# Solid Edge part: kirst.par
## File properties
Username: Kasutaja
Author: Kasutaja
Template: Iso Metric Part.par
Last saved by: Kasutaja
Revision: 8
Application: Solid Edge
Accuracy: 0,990
Face Style: Model Default
Fill Style: Normal
Coef. of Thermal Exp: 0.0
Thermal Conductivity: 0.0
Specific Heat: 0.0
Modulus of Elasticity: 0.0
Poisson's Ratio: 0.0
Yield Stress: 0.0
Ultimate Stress: 0.0
Elongation: 0.0
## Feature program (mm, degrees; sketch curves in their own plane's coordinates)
sketch used by "unnamed Protrusion 1" plane through (0, 0, 0) normal (0, 0, 1) x-axis (1, 0, 0)
  line (-7.5, 10) -> (7.5, 10)
  line (7.5, 10) -> (7.5, -10)
  line (7.5, -10) -> (-7.5, -10)
  line (-7.5, -10) -> (-7.5, 10)
  dimension (linear) = 7.5
  dimension (linear) = 7.5
extrude "unnamed Protrusion 1" add finite 20 along +normal
thinwall "Thinwall_2"  Thickness = 1 mm
draft "Draft_9"  Angles1 = 8 deg
fillet "Round_2" radius 3
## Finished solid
Body 1: solid body, 23 faces, 48 edges, 28 vertices.
  Faces by surface: plane 11, cylinder 8, sphere 4
  Edges by curve: line 32, circle 12, ellipse 4
Bounding box of the edges (mm; curved faces can reach further): 20.622 x 25.622 x 20.000, from (-10.3108, -12.8108, 0) to (10.3108, 12.8108, 20).
Cylindrical faces by radius (mm): R3 x8
Spherical faces by radius (mm): R3 x4
Planar faces by outward normal: +x 1, +y 1, +z 1, -x 1, -y 1, -z 2, oblique 4
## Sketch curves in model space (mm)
line (7.5, 10, 0) -> (7.5, -10, 0)
line (7.5, -10, 0) -> (-7.5, -10, 0)
line (-7.5, -10, 0) -> (-7.5, 10, 0)
line (-7.5, 10, 0) -> (7.5, 10, 0)
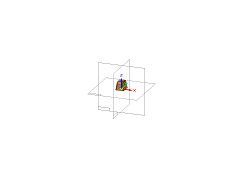
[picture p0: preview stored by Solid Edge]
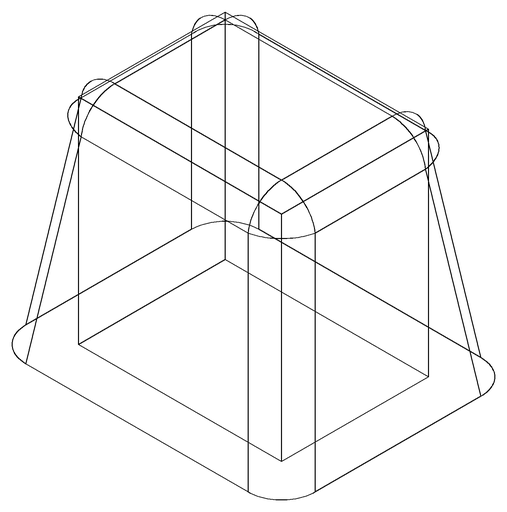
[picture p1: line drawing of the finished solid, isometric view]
